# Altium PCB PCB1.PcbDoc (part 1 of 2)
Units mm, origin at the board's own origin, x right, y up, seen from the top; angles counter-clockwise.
Board outline 100 x 100 mm, 4 copper layers (Top Layer, Layer 1, Layer 2, Bottom Layer), stack 1.55 mm thick; 90 components, 49 nets, 314 pads, 474 vias.
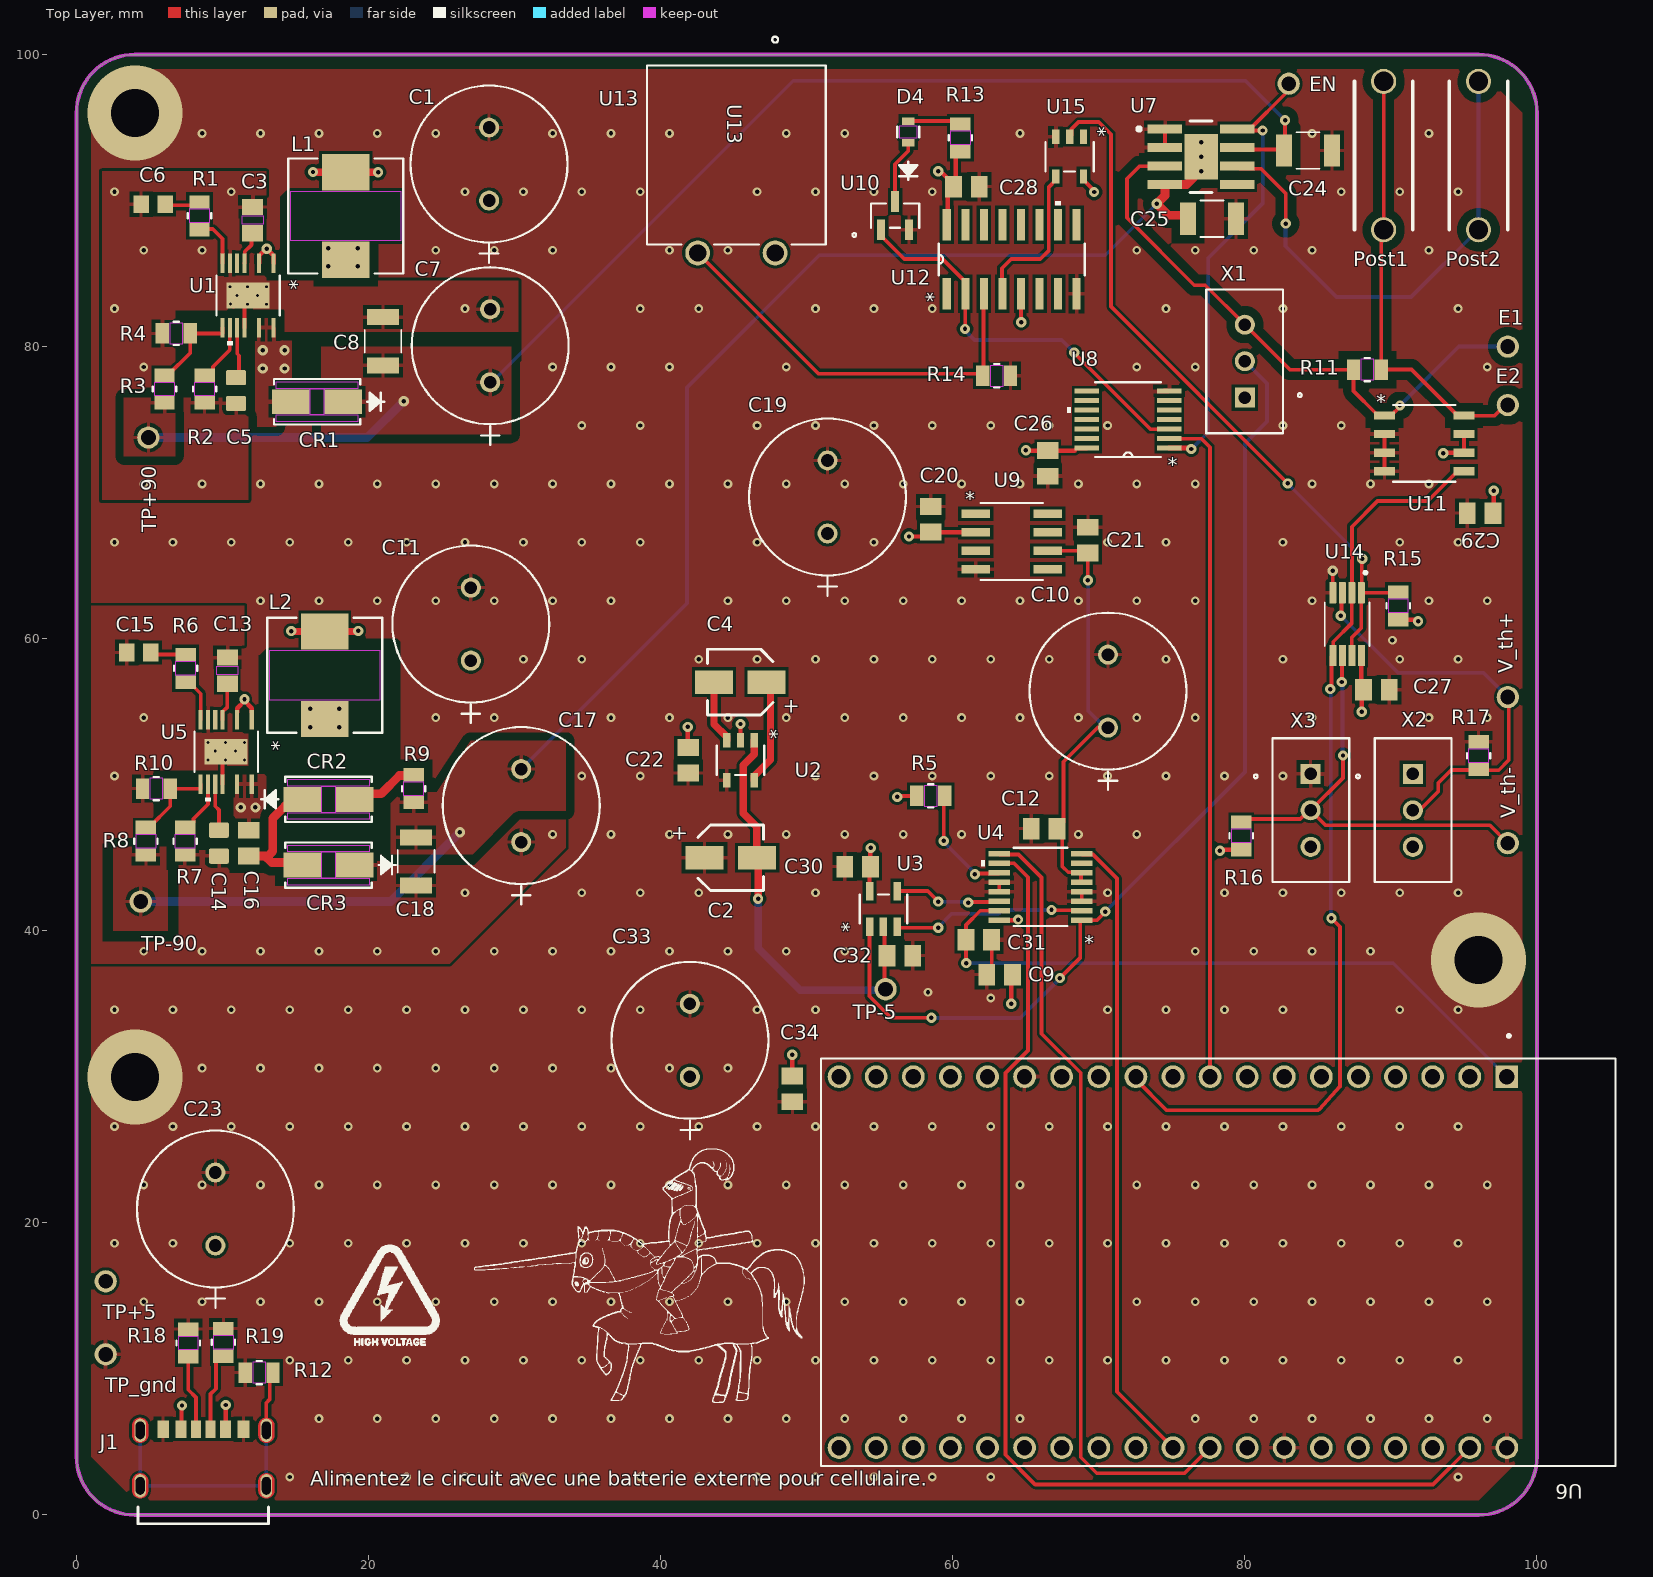
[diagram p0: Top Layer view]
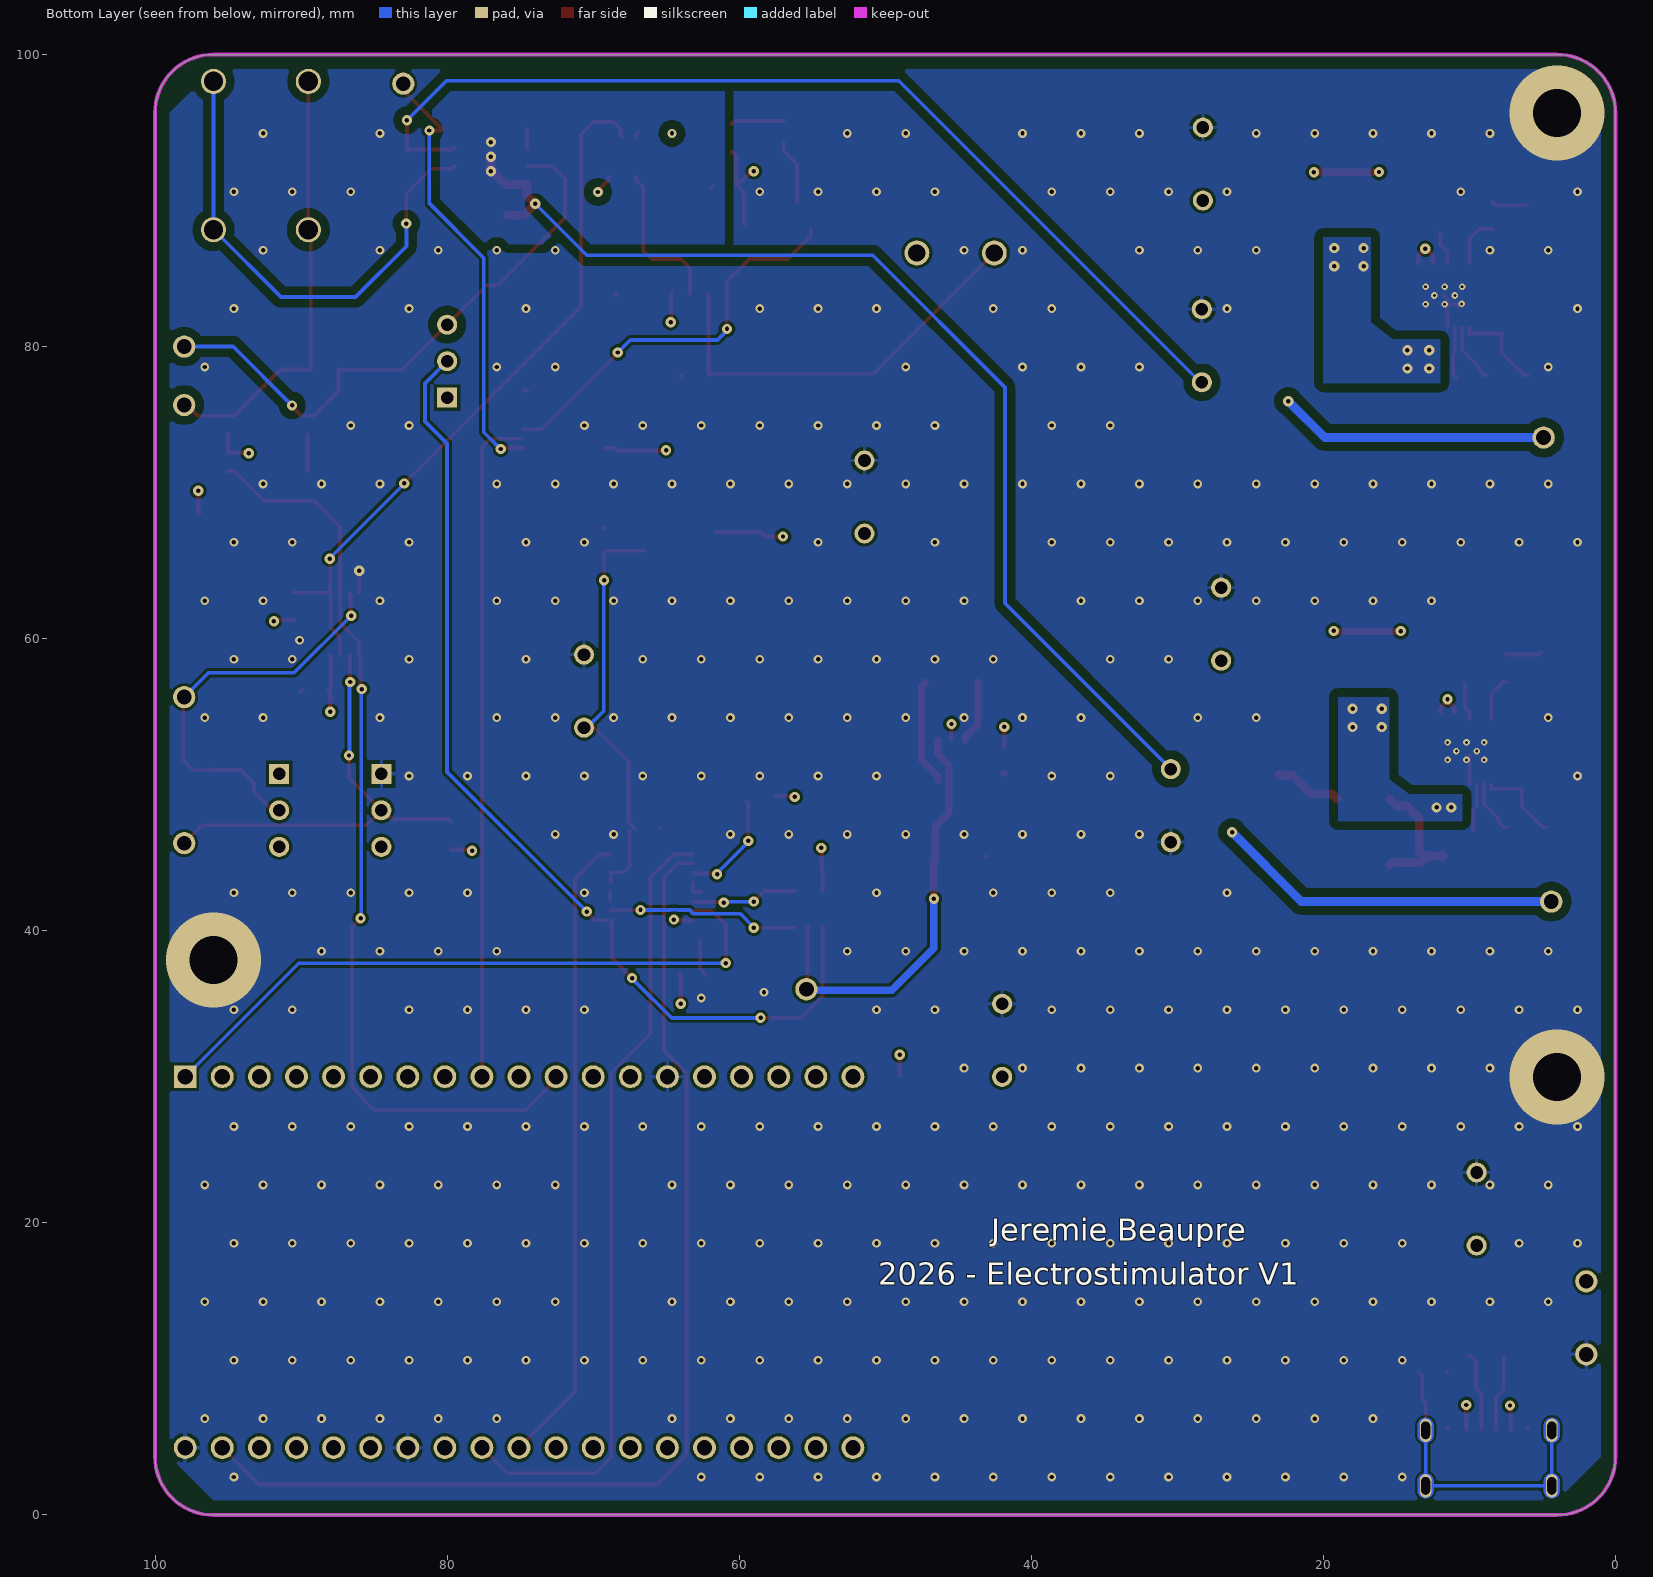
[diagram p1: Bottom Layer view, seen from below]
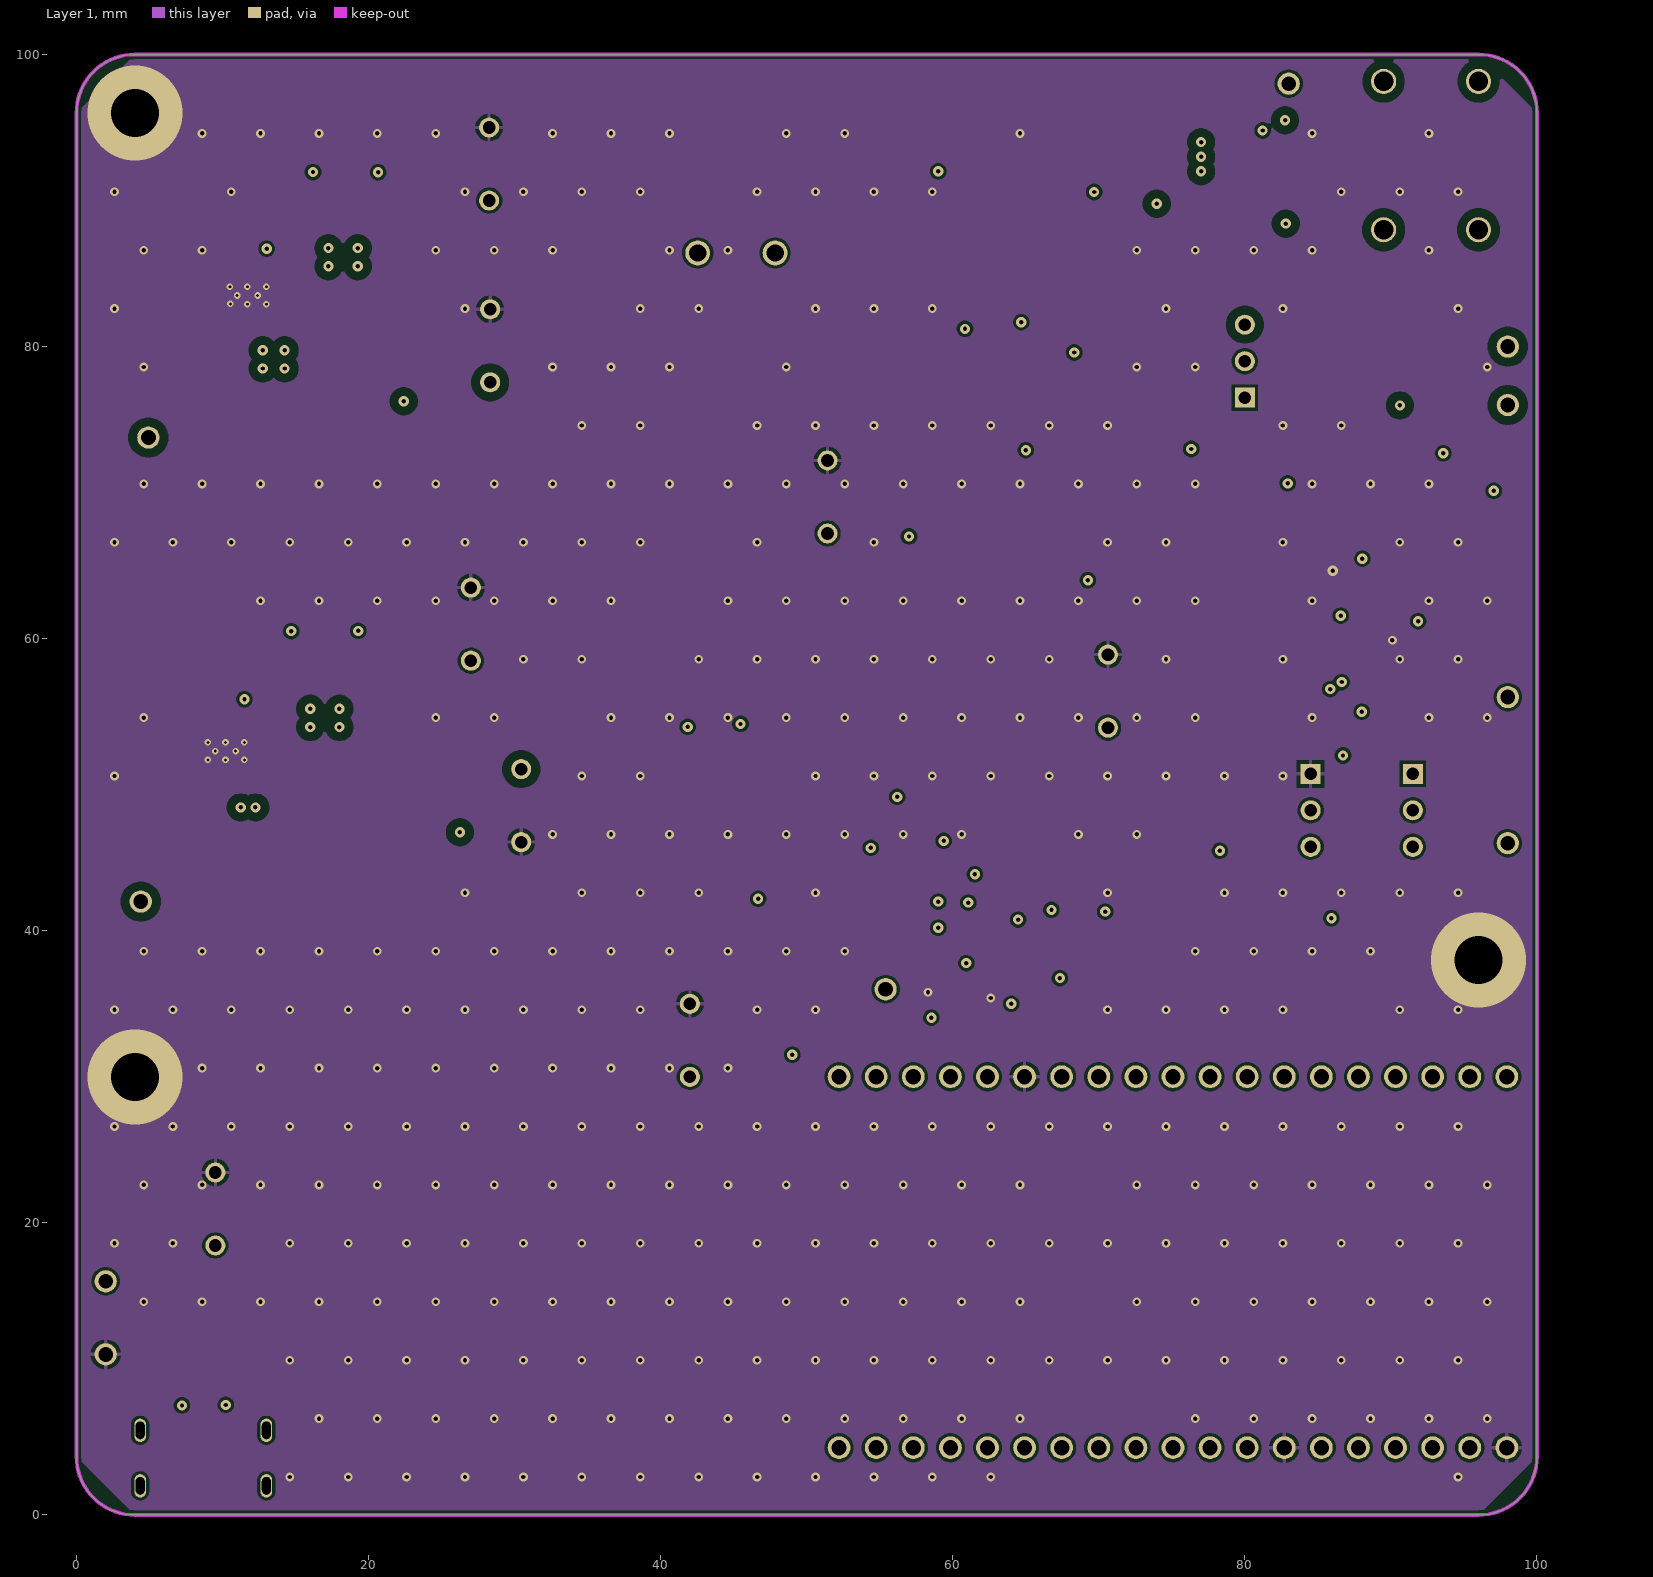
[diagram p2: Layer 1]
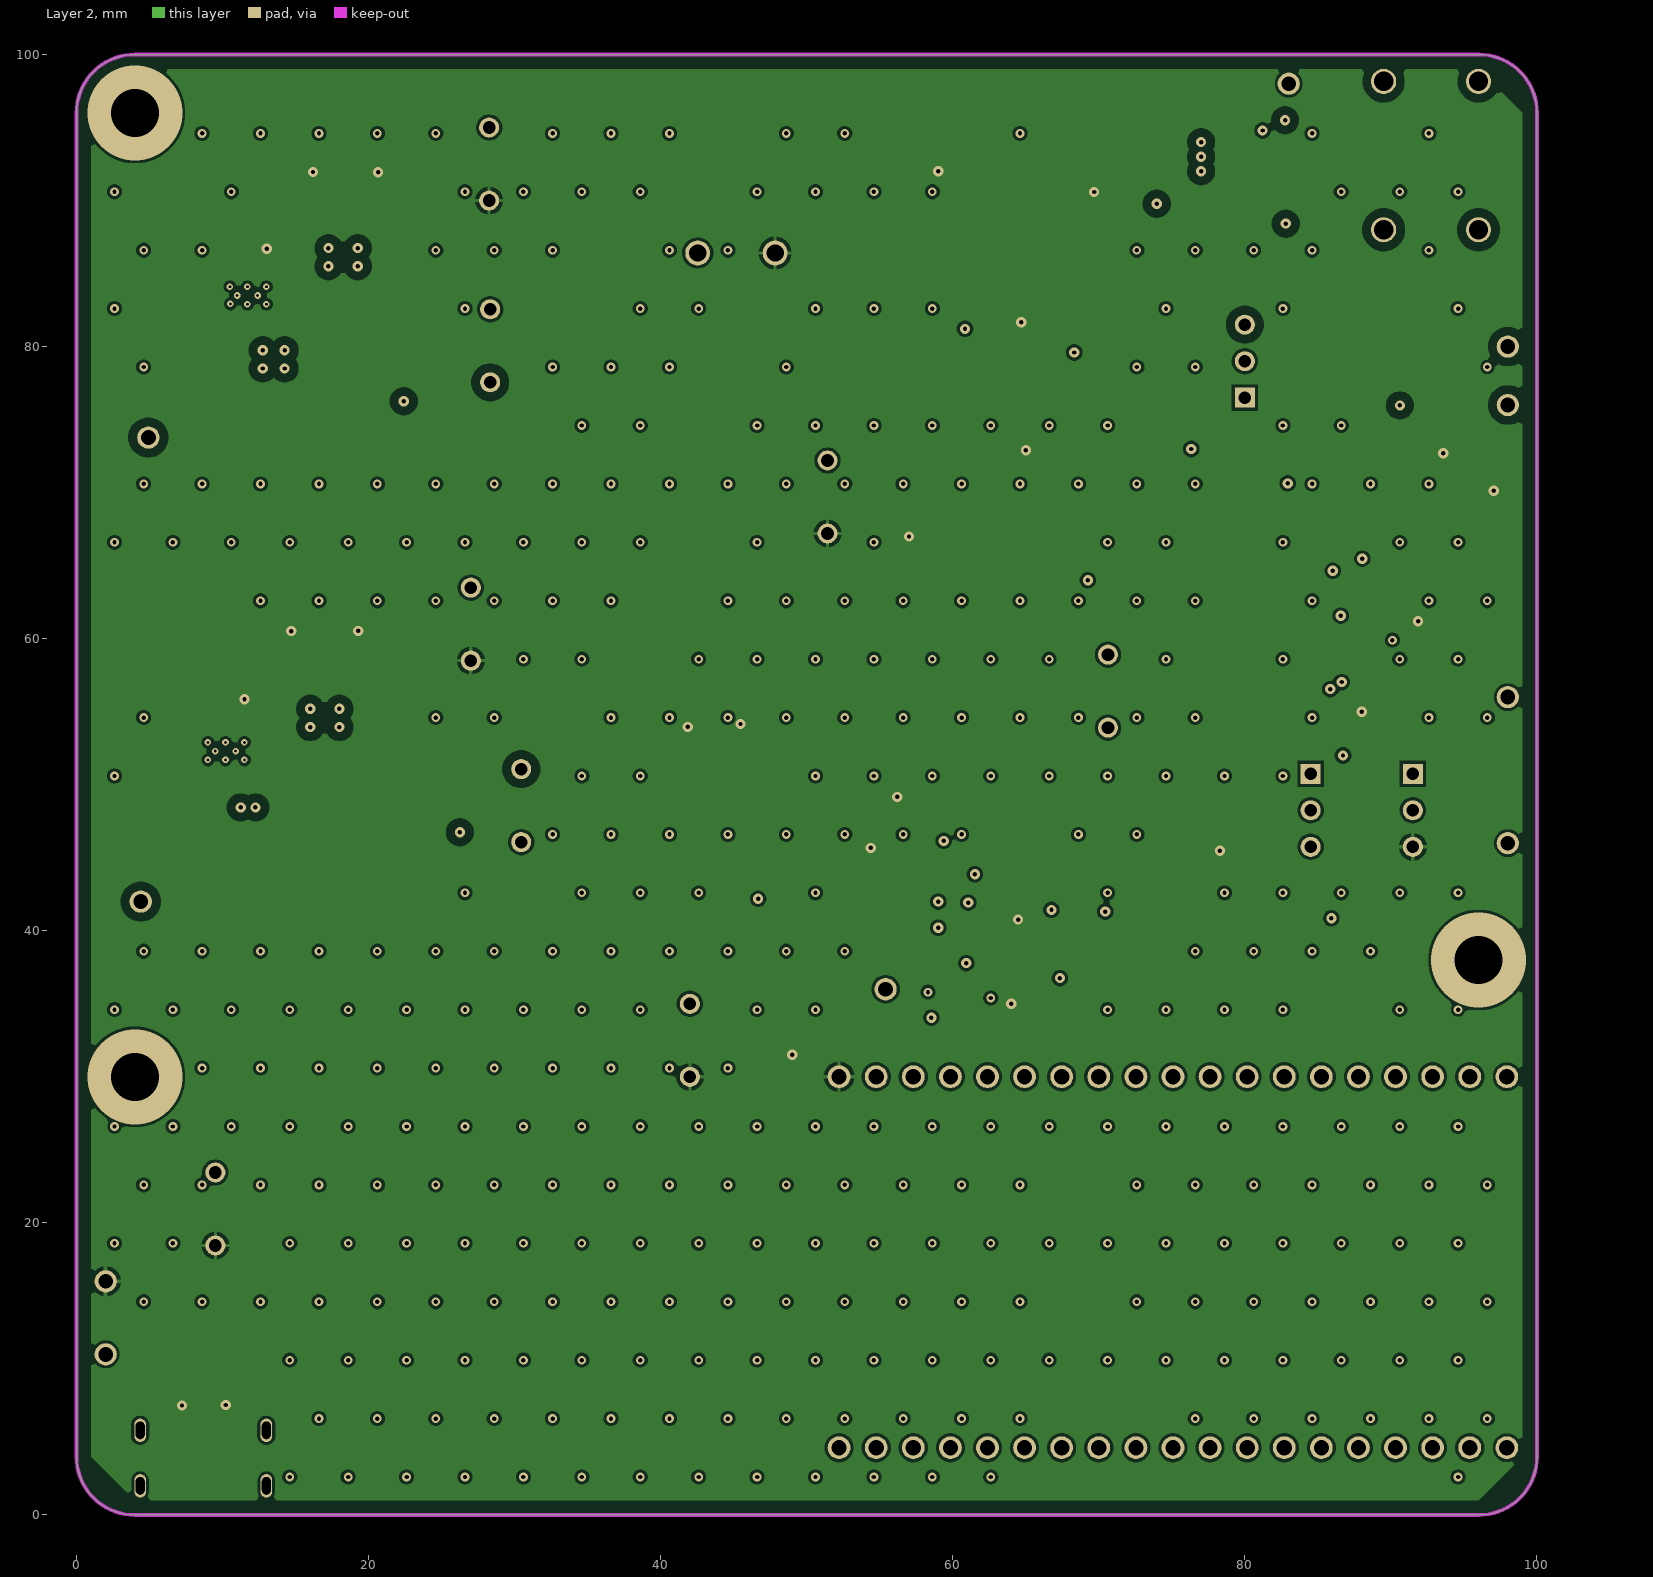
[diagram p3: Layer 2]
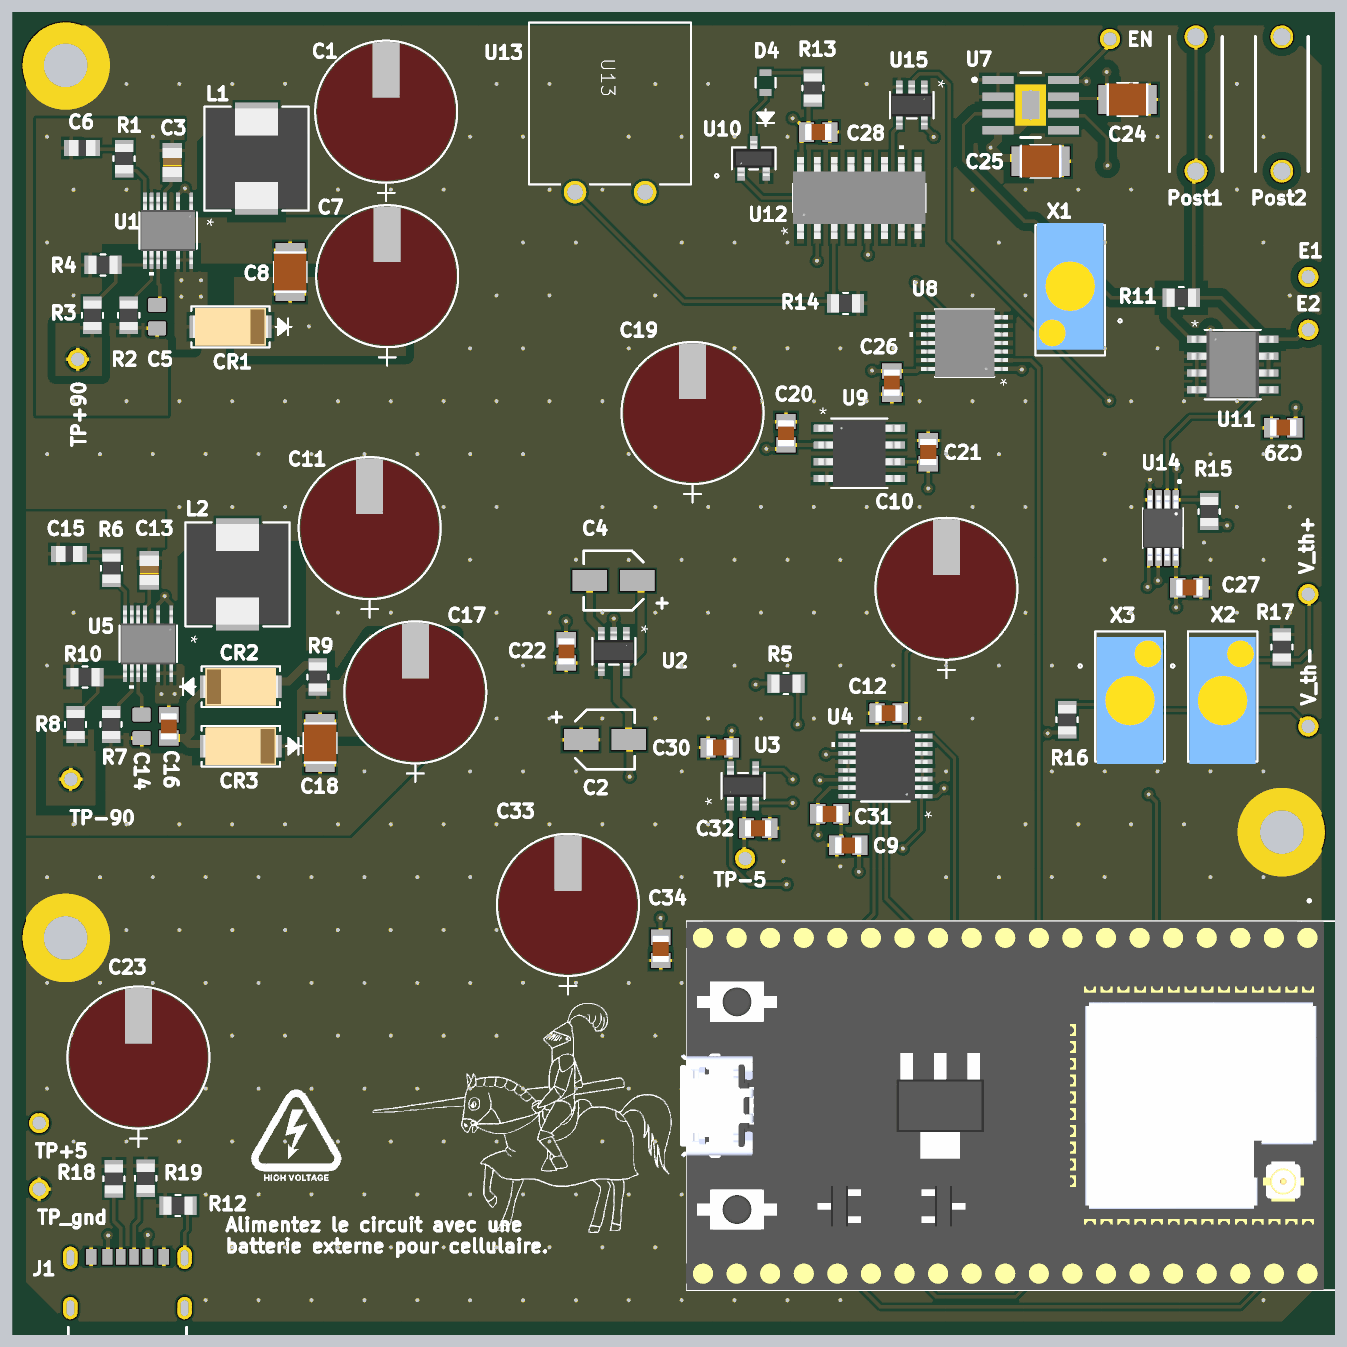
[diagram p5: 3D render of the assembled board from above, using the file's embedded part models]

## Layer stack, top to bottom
Top Solder: solder mask 0.0102, Solder Resist, Dk 3.5
Top Layer: signal copper 0.035
Dielectric 2: prepreg 0.19, PP-006, Dk 4.1
Layer 1: signal copper 0.035
Dielectric 1: core 1.03, Core-006, Dk 4.2
Layer 2: signal copper 0.035
Dielectric 3: prepreg 0.19, PP-006, Dk 4.1
Bottom Layer: signal copper 0.035
Bottom Solder: solder mask 0.0102, Solder Resist, Dk 3.5

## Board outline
0,4 0,96 cw(c4,96) 4,100 96,100 cw(c96,96) 100,96 100,4 cw(c96,4) 96,0 4,0 cw(c4,4)

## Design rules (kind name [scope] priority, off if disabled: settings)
Clearance HighVoltage [InNetClass('HighVoltage')] p1: gap=0.6 ignorepadtopadclearanceinfootprint=TRUE except(0.01: SMDPad-Region Region-Region; 0.152: Arc-Region Arc-Text Arc-Hole Track-Region Track-Text Track-Hole SMDPad-Text SMDPad-Hole THPad-Region THPad-Text THPad-Hole Via-Region Via-Text Via-Hole Fill-Region Fill-Text Fill-Hole Poly-Region Poly-Text Poly-Hole Region-Text Region-Hole Text-Text Text-Hole)
Clearance [All] p2: gap=0.2 ignorepadtopadclearanceinfootprint=TRUE except(0.01: SMDPad-Region Region-Region; 0.152: Track-Region)
HoleSize [All] p1: absolutevalues=TRUE maxlimit=6 minlimit=0.025 maxpercent=80.000 minpercent=20.000
MinimumSolderMaskSliver [All] p1: minsoldermaskwidth=0.1
PolygonConnect [All] p1: thpad.connectstyle=Relief thpad.reliefconductorwidth=0.254 thpad.reliefentries=4 thpad.polygonreliefangle="90 Angle" thpad.airgapwidth=0.254 smdpad.connectstyle=Relief smdpad.reliefconductorwidth=0.254 smdpad.reliefentries=4 smdpad.polygonreliefangle="90 Angle" smdpad.airgapwidth=0.254 via.connectstyle=Direct via.reliefconductorwidth=0.254 via.reliefentries=4 via.polygonreliefangle="90 Angle" via.airgapwidth=0.254
RoutingVias RoutingVias_small [All] p1: holewidth=0.3 width=0.7 viastyle="Through Hole" minholewidth=0.3 minwidth=0.7 maxholewidth=0.3 maxwidth=0.7
RoutingVias [All] p2: holewidth=0.711 width=6 viastyle="Through Hole" minholewidth=0.5 minwidth=0.7 maxholewidth=6 maxwidth=8
SolderMaskExpansion [All] p1: expansion=0.102 istentingtop=FALSE
SupplyNets "Schematic Supply Nets_17" [InNet('S1')] p1: voltage=0.000
SupplyNets "Schematic Supply Nets_16" [InNet('-5')] p2: voltage=0.000
SupplyNets "Schematic Supply Nets_15" [InNet('Electrode -')] p3: voltage=0.000
SupplyNets "Schematic Supply Nets_14" [InNet('EN_OPA2')] p4: voltage=0.000
SupplyNets "Schematic Supply Nets_13" [InNet('+5')] p5: voltage=0.000
SupplyNets "Schematic Supply Nets_12" [InNet('+90')] p6: voltage=0.000
SupplyNets "Schematic Supply Nets_11" [InNet('DIN')] p7: voltage=0.000
SupplyNets "Schematic Supply Nets_10" [InNet('+2.5')] p8: voltage=0.000
SupplyNets "Schematic Supply Nets_9" [InNet('V_th+')] p9: voltage=0.000
SupplyNets "Schematic Supply Nets_8" [InNet('CS')] p10: voltage=0.000
SupplyNets "Schematic Supply Nets_7" [InNet('+3.3')] p11: voltage=0.000
SupplyNets "Schematic Supply Nets_6" [InNet('Electrode +')] p12: voltage=0.000
SupplyNets "Schematic Supply Nets_5" [InNet('GND')] p13: voltage=0.000
SupplyNets "Schematic Supply Nets_4" [InNet('V_th-')] p14: voltage=0.000
SupplyNets "Schematic Supply Nets_3" [InNet('INV')] p15: voltage=0.000
SupplyNets "Schematic Supply Nets_2" [InNet('EN_OPA')] p16: voltage=0.000
SupplyNets "Schematic Supply Nets_1" [InNet('CLK')] p17: voltage=0.000
SupplyNets "Schematic Supply Nets" [InNet('-90')] p18: voltage=0.000
Width Power [InNet('+5')] p1: maxlimit=0.6 minlimit=0.3 preferedwidth=0.3 midlayer1_maxwidth=0.3 midlayer2_maxwidth=0.3 bottomlayer_maxwidth=0.3 minimp=50.000000 maximp=50.000000 favimp=50.000000
Width [All] p2: maxlimit=0.6 minlimit=0.2 preferedwidth=0.254
28 further rules are at their usual default settings.

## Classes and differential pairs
net class HighVoltage: +90 -90 "Electrode +" "Electrode -" NetC16_1 NetC16_2 NetCR1_2 NetCR2_2 NetE2_1
component class Sheet2: C27 C28 C29 D4 E1 E2 Post1 Post2 R11 R13 R14 R15 R16 R17 U10 U11 U12 U13 U14 U15 V_th+ V_th- X2 X3
component class Sheet1: C1 C2 C3 C4 C5 C6 C7 C8 C9 C10 C11 C12 C13 C14 C15 C16 C17 C18 C19 C20 C21 C22 C23 C24 C25 C26 C30 C31 C32 C33 C34 CR1 CR2 CR3 EN J1 L1 L2 R1 R2 R3 R4 R5 R6 R7 R8 R9 R10 R12 R18 R19 TP+5 TP+90 TP-5 TP-90 TP_gnd U1 U2 U3 U4 U5 U6 U7 U8 U9 X1

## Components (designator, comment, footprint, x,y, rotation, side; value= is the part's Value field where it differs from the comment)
C1 "10u" CAP_BX_10x20_RUB 28.25,90 r90 top
C2 "WCAP-ASLL_4X5.5" WCAP-ASLL_4X5.5(DXL) 44.8,45 r180 top
C3 "Capacitor" 0805_AVX 12.062,88.658 r90 top value=1u
C4 "WCAP-ASLL_4X5.5" WCAP-ASLL_4X5.5(DXL) 45.447,57.028 r0 top
C5 "Capacitor" CAPC2012X75N 10.922,76.992 r90 top value=2n
C6 "Capacitor" CC0805N_YAG 5.25,89.75 r0 top value=1n
C7 "10u" CAP_BX_10x20_RUB 28.324,77.556 r90 top
C8 "Capacitor" CAP_C3225X7R2E224K200AA 20.983,80.366 r270 top value=0.22u
C9 "Capacitor" CAPC2012X150N 63.2,37 r0 top value=0.1u
C10 "10u" CAP_BX_10x20_RUB 70.625,53.911 r90 top
C11 "10u" CAP_BX_10x20_RUB 27,58.5 r90 top
C12 "Capacitor" CAPC2012X150N 66.25,47 r0 top value=0.1u
C13 "Capacitor" 0805_AVX 10.33,57.807 r90 top value=1u
C14 "Capacitor" CAPC2012X75N 9.75,46 r90 top value=2n
C15 "Capacitor" CC0805N_YAG 4.268,59.049 r0 top value=1n
C16 "Capacitor" CAPC2012X150N 11.807,46.006 r90 top value=0.1u
C17 "10u" CAP_BX_10x20_RUB 30.45,46.073 r90 top
C18 "Capacitor" CAP_C3225X7R2E224K200AA 23.25,44.75 r90 top value=0.22u
C19 "10u" CAP_BX_10x20_RUB 51.423,67.205 r90 top
C20 "Capacitor" CAPC2012X150N 58.491,68.177 r270 top value=0.1u
C21 "Capacitor" CAPC2012X150N 69.25,66.75 r270 top value=0.1u
C22 "Capacitor" CAPC2012X150N 41.874,51.679 r270 top value=0.1u
C23 "10u" CAP_BX_10x20_RUB 9.509,18.452 r90 top
C24 "Capacitor" CAP_C3225X7R2E224K200AA 84.323,93.423 r180 top value=0.22u
C25 "Capacitor" CAP_C3225X7R2E224K200AA 77.75,88.75 r0 top value=0.22u
C26 "Capacitor" CAPC2012X150N 66.5,72 r270 top value=0.1u
C27 "Capacitor" CAPC2012X150N 89,56.5 r180 top value=0.1u
C28 "Capacitor" CAPC2012X150N 60.93,90.958 r180 top value=0.1u
C29 "Capacitor" CAPC2012X150N 96.1,68.6 r0 top value=0.1u
C30 "Capacitor" CAPC2012X150N 53.48,44.4 r0 top value=0.1u
C31 "Capacitor" CAPC2012X150N 61.779,39.383 r180 top value=0.1u
C32 "Capacitor" CAPC2012X150N 56.38,38.3 r180 top value=0.1u
C33 "10u" CAP_BX_10x20_RUB 42,30 r90 top
C34 "Capacitor" CAPC2012X150N 49.017,29.174 r90 top value=0.1u
CR1 "SK220ATR" DIODE_SK220ATR_SMC-M 16.473,76.224 r180 top
CR2 "SK220ATR" DIODE_SK220ATR_SMC-M 17.25,49 r0 top
CR3 "SK220ATR" DIODE_SK220ATR_SMC-M 17.25,44.5 r180 top
D4 "SML-M13UTT86" LED_SML-M13DT_ROM 56.949,94.694 r90 top
E1 "Testpoint_1" Testpoint1 98,80 r0 top
E2 "Testpoint_1" Testpoint1 98,76 r0 top
EN "Testpoint_1" Testpoint1 83,98 r0 top
J1 "USB4125-GF-A_REVA2" GCT_USB4125-GF-A_REVA2 8.68,2.8 r0 top
L1 "Inductor" DR73 18.44,88.946 r270 top value=10u
L2 "Inductor" DR73 17,57.5 r270 top value=10u
Post1 "J110-ND" J110-ND 89.5,88 r90 top
Post2 "J110-ND" J110-ND 96,88 r90 top
R1 "Resistor" RESISTOR_0805-M 8.422,88.946 r270 top value=84.5K
R2 "Resistor" RESISTOR_0805-M 8.774,77.097 r90 top value=107K
R3 "Resistor" RESISTOR_0805-M 6.028,77.097 r270 top value=1MEG
R4 "Resistor" RESISTOR_0805-M 6.829,80.903 r180 top value=18.1K
R5 "Resistor" RESISTOR_0805-M 58.491,49.234 r0 top value=10k
R6 "Resistor" RESISTOR_0805-M 7.467,57.968 r270 top value=84.5K
R7 "Resistor" RESISTOR_0805-M 7.436,46.146 r90 top value=107K
R8 "1MEG" RESISTOR_0805-M 4.751,46.146 r90 top
R9 "Resistor" RESISTOR_0805-M 23.085,49.735 r270 top value=20
R10 "Resistor" RESISTOR_0805-M 5.467,49.735 r180 top value=8.96k
R11 "Resistor" RESISTOR_0805-M 88.391,78.427 r0 top value=1
R12 "Resistor" RESISTOR_0805-M 12.5,9.75 r180 top value=1MEG
R13 "Resistor" RESISTOR_0805-M 60.524,94.288 r270 top value=350
R14 "Resistor" RESISTOR_0805-M 63,78 r0 top value=10K
R15 "Resistor" RESISTOR_0805-M 90.5,62.25 r270 top value=10K
R16 "Resistor" RESISTOR_0805-M 79.75,46.5 r270 top value=1K
R17 "Resistor" RESISTOR_0805-M 96,52 r270 top value=1K
R18 "Resistor" RESISTOR_0805-M 7.651,11.776 r270 top value=5.1k
R19 "Resistor" RESISTOR_0805-M 10.058,11.815 r270 top value=5.1k
TP+5 "Testpoint_1" Testpoint1 2,16 r90 top
TP+90 "Testpoint_1" Testpoint1 4.921,73.772 r0 top
TP-5 "Testpoint_1" Testpoint1 55.4,36 r270 top
TP-90 "Testpoint_1" Testpoint1 4.4,42 r90 top
TP_gnd "Testpoint_1" Testpoint1 2,11 r90 top
U1 "LT8365HMSE#PBF" 05-08-1871_ADI 11.75,83.5 r270 top
U2 "MAX870EUK+T" 21-0057F_MXM 45.467,51.679 r270 top
U3 "AD8628ARTZ-REEL7" RJ_5_ADI 55.25,41.5 r90 top
U4 "AD5542ABRUZ" RU_16_ADI 66,43 r180 top
U5 "LT8365HMSE#PBF" 05-08-1871_ADI 10.25,52.25 r270 top
U6 "ESP32-DEVKITC-32UE" ESPRESSIF_ESP32-DEVKITC-32UE 75.075,17.308 r270 top
U7 "OPA462IDDA" DDA0008J-IPC_A 77,93 r0 top
U8 "SN74HC02PWR" PW14 72,75 r180 top
U9 "ADR421ARZ" R_8_ADI 64.036,66.655 r0 top
U10 "2N7002KT1G" SOT-23_ONS 56.048,88.965 r0 top
U11 "INA240A1DR" D8_TEX 92.281,73.37 r0 top
U12 "CD4043BDR" D16 64.036,85.979 r90 top
U13 "GPTS203211B" SWITCH_03211B 47.834,86.411 r270 top
U14 "TLV1702AIDGKR" SOP65P490X110-8N 87,61 r270 top
U15 "SN74AHC1G04DBVR" DBV5 68,93 r270 top
V_th+ "Testpoint_1" Testpoint1 98,56 r270 top
V_th- "Testpoint_1" Testpoint1 98,46 r270 top
X1 "PV36W102C01B00" POT_PV36W_MUR 80,76.5 r90 top
X2 "PV36W102C01B00" POT_PV36W_MUR 91.5,50.75 r270 top
X3 "PV36W102C01B00" POT_PV36W_MUR 84.5,50.75 r270 top

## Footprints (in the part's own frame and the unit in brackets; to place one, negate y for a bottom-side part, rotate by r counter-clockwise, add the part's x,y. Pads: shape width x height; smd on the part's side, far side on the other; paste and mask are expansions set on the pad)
05-08-1871_ADI [mil]
  rect 52.5x11 smd paste+0 mask+0: 1(-87.25,68.9) 3(-87.25,29.53) 5(-87.25,-9.84) 6(-87.25,-29.53) 7(-87.25,-49.21) 8(-87.25,-68.9) 9(87.25,-68.9) 10(87.25,-49.21) 11(87.25,-29.53) 12(87.25,-9.84) 14(87.25,29.53) 16(87.25,68.9)
  rect 69x116 smd paste-57.5 mask+0: 17(0,0)
  silkscreen extent -54,-86 134,86, body extent -99,-81 99,81, height 43
21-0057F_MXM [mil]
  rect 38.5x20 smd paste+0 mask+0: 1(-53.75,37.4) 2(-53.75,0) 3(-53.75,-37.4) 4(53.75,-37.4) 5(53.75,37.4)
  silkscreen extent -40,-64 40,64, body extent -59,-59 59,59, height 57
0805_AVX [mil]
  rect 44x57 smd paste+0 mask+0: 1(-35.5,0) 2(35.5,0)
  Top Layer keep-out region: -11.5,-28.5 -11.5,28.5 11.5,28.5 11.5,-28.5
  body extent -44,-29 44,29, height 37
CAP_BX_10x20_RUB [mil]
  round 54 hole 34 paste-99999 mask+0: 1(0,0) 2(196.85,0)
  silkscreen extent -168,-212 310,212, body extent -108,-206 306,206, height 867
CAP_C3225X7R2E224K200AA [mm]
  rect 1.1x2.2 smd: 1(-1.65,0) 2(1.65,0)
  silkscreen extent -0.78,-1.25 0.78,1.25, body extent -1.6,-1.25 1.6,1.25, height 2.2
CAPC2012X75N [mm]
  rrect25% 1.05x1.38 smd: 1(-0.888,0) 2(0.888,0)
CAPC2012X150N [mm]
  rect 1.15x1.47 smd: 1(-0.88,0) 2(0.88,0)
  body extent -1,-0.63 1,0.63, height 1.5
CC0805N_YAG [mil]
  rect 42x48 smd paste+0 mask+0: 1(-32.5,0) 2(32.5,0)
  body extent -39,-24 39,24, height 28
D8_TEX [mm]
  rect 1.455x0.558 smd paste+0 mask+0: 1(-2.721,1.905) 2(-2.721,0.635) 3(-2.721,-0.635) 4(-2.721,-1.905) 5(2.721,-1.905) 6(2.721,-0.635) 7(2.721,0.635) 8(2.721,1.905)
  silkscreen extent -2.12,-2.63 2.12,2.63, body extent -3.1,-2.5 3.1,2.5, height 1.76
D16 [mil]
  rect 86x22 smd paste-43 mask-43: 1(-93,175) 2(-93,125) 3(-93,75) 4(-93,25) 5(-93,-25) 6(-93,-75) 7(-93,-125) 8(-93,-175) 9(93,-175) 10(93,-125) 11(93,-75) 12(93,-25) 13(93,25) 14(93,75) 15(93,125) 16(93,175)
  silkscreen extent -43,-197 156,197, body extent -122,-197 122,197, height 69
DBV5 [mil]
  rect 38.28x20 smd paste+0 mask+0: 1(-53.64,37.4) 2(-53.64,0) 3(-53.64,-37.4) 4(53.64,-37.4) 5(53.64,37.4)
  silkscreen extent -40,-65 40,65, body extent -59,-60 59,60, height 57
DDA0008J-IPC_A [mm]
  rect 2.353x0.622 smd paste+0 mask+0: 1(-2.477,1.905) 2(-2.477,0.635) 3(-2.477,-0.635) 4(-2.477,-1.905) 5(2.477,-1.905) 6(2.477,-0.635) 7(2.477,0.635) 8(2.477,1.905)
  rect 2.3x3.1 smd paste-1.537 mask+0: 9(0,0)
  silkscreen extent -4.37,-2.45 0.75,2.45
DIODE_SK220ATR_SMC-M [mil]
  rect 101x67 smd paste+0 mask+0: 1(-71,0) 2(71,0)
  Top Layer keep-out region: -18.5,-35.5 -18.5,35.5 18.5,35.5 18.5,-35.5
  Top Layer keep-out region: -109.5,35.5 -109.5,54 109.5,54 109.5,35.5
  Top Layer keep-out region: -109.5,-54 -109.5,-35.5 109.5,-35.5 109.5,-54
  silkscreen extent -182,-61 117,61, body extent -111,-56 111,56, height 118
DR73 [mil]
  rect 98x128 smd paste+0 mask+0: 1(-118,0) 2(118,0)
  Top Layer keep-out region: -67,-148 -67,148 67,148 67,-148
  silkscreen extent -155,-155 155,155, body extent -150,-150 150,150, height 140
ESPRESSIF_ESP32-DEVKITC-32UE [mm]
  rect 1.56x1.56 / inner round 1.56 / far side rect 1.56x1.56 hole 1.04: 1(-12.7,22.86)
  round 1.56 hole 1.04: 2(-12.7,20.32) 3(-12.7,17.78) 4(-12.7,15.24) 5(-12.7,12.7) 6(-12.7,10.16) 7(-12.7,7.62) 8(-12.7,5.08) 9(-12.7,2.54) 10(-12.7,0) 11(-12.7,-2.54) 12(-12.7,-5.08) 13(-12.7,-7.62) 14(-12.7,-10.16) 15(-12.7,-12.7) 16(-12.7,-15.24) 17(-12.7,-17.78) 18(-12.7,-20.32) 19(-12.7,-22.86) 20(12.7,22.86) 21(12.7,20.32) 22(12.7,17.78) 23(12.7,15.24) 24(12.7,12.7) 25(12.7,10.16) 26(12.7,7.62) 27(12.7,5.08) 28(12.7,2.54) 29(12.7,0) 30(12.7,-2.54) 31(12.7,-5.08) 32(12.7,-7.62) 33(12.7,-10.16) 34(12.7,-12.7) 35(12.7,-15.24) 36(12.7,-17.78) 37(12.7,-20.32) 38(12.7,-22.86)
  silkscreen extent -15.6,-24.1 13.95,30.3, body extent -13.95,-24.62 13.95,24.13, height 7.85
GCT_USB4125-GF-A_REVA2 [mm]
  rect 0.7x1.2 smd: A5(-0.5,3.08) B5(0.5,3.08)
  rect 0.76x1.2 smd: A9(1.52,3.08) B9(-1.52,3.08)
  rect 0.8x1.2 smd: A12(2.75,3.08) B12(-2.75,3.08)
  oval 0.8x1.6 hole 0.6 slot 1.2 at 90 deg mask+0: S1(-4.32,3) S2(4.32,3) S3(-4.32,-0.8) S4(4.32,-0.8)
  Top Layer region: 4.349,0.049 4.377,0.047 4.406,0.043 4.434,0.038 4.462,0.031 4.49,0.023 4.517,0.013 4.544,0.002 4.57,-0.01 4.595,-0.024 4.62,-0.039 4.643,-0.055 4.666,-0.073 4.688,-0.091 4.709,-0.111 4.729,-0.132 4.747,-0.154 4.765,-0.177 4.781,-0.2 4.796,-0.225 4.81,-0.25 4.822,-0.276 4.833,-0.303 4.843,-0.33 4.851,-0.358 4.858,-0.386 4.863,-0.414 4.867,-0.443 4.869,-0.471 4.87,-0.5 4.87,-1.1 4.869,-1.129 4.867,-1.157 4.863,-1.186 4.858,-1.214 4.851,-1.242 4.843,-1.27 4.833,-1.297 4.822,-1.324 4.81,-1.35 4.796,-1.375 4.781,-1.4 4.765,-1.423 4.747,-1.446 4.729,-1.468 4.709,-1.489 4.688,-1.509 4.666,-1.527 4.643,-1.545 4.62,-1.561 4.595,-1.576 4.57,-1.59 4.544,-1.602 4.517,-1.613 4.49,-1.623 4.462,-1.631 4.434,-1.638 4.406,-1.643 4.377,-1.647 4.349,-1.649 4.32,-1.65 4.291,-1.649 4.263,-1.647 4.234,-1.643 4.206,-1.638 4.178,-1.631 4.15,-1.623 4.123,-1.613 4.096,-1.602 4.07,-1.59 4.045,-1.576 4.02,-1.561 3.997,-1.545 3.974,-1.527 3.952,-1.509 3.931,-1.489 3.911,-1.468 3.893,-1.446 3.875,-1.423 3.859,-1.4 3.844,-1.375 3.83,-1.35 3.818,-1.324 3.807,-1.297 3.797,-1.27 3.789,-1.242 3.782,-1.214 3.777,-1.186 3.773,-1.157 3.771,-1.129 3.77,-1.1 3.77,-0.5 3.771,-0.471 3.773,-0.443 3.777,-0.414 3.782,-0.386 3.789,-0.358 3.797,-0.33 3.807,-0.303 3.818,-0.276 3.83,-0.25 3.844,-0.225 3.859,-0.2 3.875,-0.177 3.893,-0.154 3.911,-0.132 3.931,-0.111 3.952,-0.091 3.974,-0.073 3.997,-0.055 4.02,-0.039 4.045,-0.024 4.07,-0.01 4.096,0.002 4.123,0.013 4.15,0.023 4.178,0.031 4.206,0.038 4.234,0.043 4.263,0.047 4.291,0.049 4.32,0.05
  Top Layer region: 4.349,3.849 4.377,3.847 4.406,3.843 4.434,3.838 4.462,3.831 4.49,3.823 4.517,3.813 4.544,3.802 4.57,3.79 4.595,3.776 4.62,3.761 4.643,3.745 4.666,3.727 4.688,3.709 4.709,3.689 4.729,3.668 4.747,3.646 4.765,3.623 4.781,3.6 4.796,3.575 4.81,3.55 4.822,3.524 4.833,3.497 4.843,3.47 4.851,3.442 4.858,3.414 4.863,3.386 4.867,3.357 4.869,3.329 4.87,3.3 4.87,2.7 4.869,2.671 4.867,2.643 4.863,2.614 4.858,2.586 4.851,2.558 4.843,2.53 4.833,2.503 4.822,2.476 4.81,2.45 4.796,2.425 4.781,2.4 4.765,2.377 4.747,2.354 4.729,2.332 4.709,2.311 4.688,2.291 4.666,2.273 4.643,2.255 4.62,2.239 4.595,2.224 4.57,2.21 4.544,2.198 4.517,2.187 4.49,2.177 4.462,2.169 4.434,2.162 4.406,2.157 4.377,2.153 4.349,2.151 4.32,2.15 4.291,2.151 4.263,2.153 4.234,2.157 4.206,2.162 4.178,2.169 4.15,2.177 4.123,2.187 4.096,2.198 4.07,2.21 4.045,2.224 4.02,2.239 3.997,2.255 3.974,2.273 3.952,2.291 3.931,2.311 3.911,2.332 3.893,2.354 3.875,2.377 3.859,2.4 3.844,2.425 3.83,2.45 3.818,2.476 3.807,2.503 3.797,2.53 3.789,2.558 3.782,2.586 3.777,2.614 3.773,2.643 3.771,2.671 3.77,2.7 3.77,3.3 3.771,3.329 3.773,3.357 3.777,3.386 3.782,3.414 3.789,3.442 3.797,3.47 3.807,3.497 3.818,3.524 3.83,3.55 3.844,3.575 3.859,3.6 3.875,3.623 3.893,3.646 3.911,3.668 3.931,3.689 3.952,3.709 3.974,3.727 3.997,3.745 4.02,3.761 4.045,3.776 4.07,3.79 4.096,3.802 4.123,3.813 4.15,3.823 4.178,3.831 4.206,3.838 4.234,3.843 4.263,3.847 4.291,3.849 4.32,3.85
  Top Layer region: -4.291,3.849 -4.263,3.847 -4.234,3.843 -4.206,3.838 -4.178,3.831 -4.15,3.823 -4.123,3.813 -4.096,3.802 -4.07,3.79 -4.045,3.776 -4.02,3.761 -3.997,3.745 -3.974,3.727 -3.952,3.709 -3.931,3.689 -3.911,3.668 -3.893,3.646 -3.875,3.623 -3.859,3.6 -3.844,3.575 -3.83,3.55 -3.818,3.524 -3.807,3.497 -3.797,3.47 -3.789,3.442 -3.782,3.414 -3.777,3.386 -3.773,3.357 -3.771,3.329 -3.77,3.3 -3.77,2.7 -3.771,2.671 -3.773,2.643 -3.777,2.614 -3.782,2.586 -3.789,2.558 -3.797,2.53 -3.807,2.503 -3.818,2.476 -3.83,2.45 -3.844,2.425 -3.859,2.4 -3.875,2.377 -3.893,2.354 -3.911,2.332 -3.931,2.311 -3.952,2.291 -3.974,2.273 -3.997,2.255 -4.02,2.239 -4.045,2.224 -4.07,2.21 -4.096,2.198 -4.123,2.187 -4.15,2.177 -4.178,2.169 -4.206,2.162 -4.234,2.157 -4.263,2.153 -4.291,2.151 -4.32,2.15 -4.349,2.151 -4.377,2.153 -4.406,2.157 -4.434,2.162 -4.462,2.169 -4.49,2.177 -4.517,2.187 -4.544,2.198 -4.57,2.21 -4.595,2.224 -4.62,2.239 -4.643,2.255 -4.666,2.273 -4.688,2.291 -4.709,2.311 -4.729,2.332 -4.747,2.354 -4.765,2.377 -4.781,2.4 -4.796,2.425 -4.81,2.45 -4.822,2.476 -4.833,2.503 -4.843,2.53 -4.851,2.558 -4.858,2.586 -4.863,2.614 -4.867,2.643 -4.869,2.671 -4.87,2.7 -4.87,3.3 -4.869,3.329 -4.867,3.357 -4.863,3.386 -4.858,3.414 -4.851,3.442 -4.843,3.47 -4.833,3.497 -4.822,3.524 -4.81,3.55 -4.796,3.575 -4.781,3.6 -4.765,3.623 -4.747,3.646 -4.729,3.668 -4.709,3.689 -4.688,3.709 -4.666,3.727 -4.643,3.745 -4.62,3.761 -4.595,3.776 -4.57,3.79 -4.544,3.802 -4.517,3.813 -4.49,3.823 -4.462,3.831 -4.434,3.838 -4.406,3.843 -4.377,3.847 -4.349,3.849 -4.32,3.85
  Top Layer region: -4.291,0.049 -4.263,0.047 -4.234,0.043 -4.206,0.038 -4.178,0.031 -4.15,0.023 -4.123,0.013 -4.096,0.002 -4.07,-0.01 -4.045,-0.024 -4.02,-0.039 -3.997,-0.055 -3.974,-0.073 -3.952,-0.091 -3.931,-0.111 -3.911,-0.132 -3.893,-0.154 -3.875,-0.177 -3.859,-0.2 -3.844,-0.225 -3.83,-0.25 -3.818,-0.276 -3.807,-0.303 -3.797,-0.33 -3.789,-0.358 -3.782,-0.386 -3.777,-0.414 -3.773,-0.443 -3.771,-0.471 -3.77,-0.5 -3.77,-1.1 -3.771,-1.129 -3.773,-1.157 -3.777,-1.186 -3.782,-1.214 -3.789,-1.242 -3.797,-1.27 -3.807,-1.297 -3.818,-1.324 -3.83,-1.35 -3.844,-1.375 -3.859,-1.4 -3.875,-1.423 -3.893,-1.446 -3.911,-1.468 -3.931,-1.489 -3.952,-1.509 -3.974,-1.527 -3.997,-1.545 -4.02,-1.561 -4.045,-1.576 -4.07,-1.59 -4.096,-1.602 -4.123,-1.613 -4.15,-1.623 -4.178,-1.631 -4.206,-1.638 -4.234,-1.643 -4.263,-1.647 -4.291,-1.649 -4.32,-1.65 -4.349,-1.649 -4.377,-1.647 -4.406,-1.643 -4.434,-1.638 -4.462,-1.631 -4.49,-1.623 -4.517,-1.613 -4.544,-1.602 -4.57,-1.59 -4.595,-1.576 -4.62,-1.561 -4.643,-1.545 -4.666,-1.527 -4.688,-1.509 -4.709,-1.489 -4.729,-1.468 -4.747,-1.446 -4.765,-1.423 -4.781,-1.4 -4.796,-1.375 -4.81,-1.35 -4.822,-1.324 -4.833,-1.297 -4.843,-1.27 -4.851,-1.242 -4.858,-1.214 -4.863,-1.186 -4.867,-1.157 -4.869,-1.129 -4.87,-1.1 -4.87,-0.5 -4.869,-0.471 -4.867,-0.443 -4.863,-0.414 -4.858,-0.386 -4.851,-0.358 -4.843,-0.33 -4.833,-0.303 -4.822,-0.276 -4.81,-0.25 -4.796,-0.225 -4.781,-0.2 -4.765,-0.177 -4.747,-0.154 -4.729,-0.132 -4.709,-0.111 -4.688,-0.091 -4.666,-0.073 -4.643,-0.055 -4.62,-0.039 -4.595,-0.024 -4.57,-0.01 -4.544,0.002 -4.517,0.013 -4.49,0.023 -4.462,0.031 -4.434,0.038 -4.406,0.043 -4.377,0.047 -4.349,0.049 -4.32,0.05
  Bottom Layer region: 4.349,3.849 4.377,3.847 4.406,3.843 4.434,3.838 4.462,3.831 4.49,3.823 4.517,3.813 4.544,3.802 4.57,3.79 4.595,3.776 4.62,3.761 4.643,3.745 4.666,3.727 4.688,3.709 4.709,3.689 4.729,3.668 4.747,3.646 4.765,3.623 4.781,3.6 4.796,3.575 4.81,3.55 4.822,3.524 4.833,3.497 4.843,3.47 4.851,3.442 4.858,3.414 4.863,3.386 4.867,3.357 4.869,3.329 4.87,3.3 4.87,2.7 4.869,2.671 4.867,2.643 4.863,2.614 4.858,2.586 4.851,2.558 4.843,2.53 4.833,2.503 4.822,2.476 4.81,2.45 4.796,2.425 4.781,2.4 4.765,2.377 4.747,2.354 4.729,2.332 4.709,2.311 4.688,2.291 4.666,2.273 4.643,2.255 4.62,2.239 4.595,2.224 4.57,2.21 4.544,2.198 4.517,2.187 4.49,2.177 4.462,2.169 4.434,2.162 4.406,2.157 4.377,2.153 4.349,2.151 4.32,2.15 4.291,2.151 4.263,2.153 4.234,2.157 4.206,2.162 4.178,2.169 4.15,2.177 4.123,2.187 4.096,2.198 4.07,2.21 4.045,2.224 4.02,2.239 3.997,2.255 3.974,2.273 3.952,2.291 3.931,2.311 3.911,2.332 3.893,2.354 3.875,2.377 3.859,2.4 3.844,2.425 3.83,2.45 3.818,2.476 3.807,2.503 3.797,2.53 3.789,2.558 3.782,2.586 3.777,2.614 3.773,2.643 3.771,2.671 3.77,2.7 3.77,3.3 3.771,3.329 3.773,3.357 3.777,3.386 3.782,3.414 3.789,3.442 3.797,3.47 3.807,3.497 3.818,3.524 3.83,3.55 3.844,3.575 3.859,3.6 3.875,3.623 3.893,3.646 3.911,3.668 3.931,3.689 3.952,3.709 3.974,3.727 3.997,3.745 4.02,3.761 4.045,3.776 4.07,3.79 4.096,3.802 4.123,3.813 4.15,3.823 4.178,3.831 4.206,3.838 4.234,3.843 4.263,3.847 4.291,3.849 4.32,3.85
  Bottom Layer region: 4.349,0.049 4.377,0.047 4.406,0.043 4.434,0.038 4.462,0.031 4.49,0.023 4.517,0.013 4.544,0.002 4.57,-0.01 4.595,-0.024 4.62,-0.039 4.643,-0.055 4.666,-0.073 4.688,-0.091 4.709,-0.111 4.729,-0.132 4.747,-0.154 4.765,-0.177 4.781,-0.2 4.796,-0.225 4.81,-0.25 4.822,-0.276 4.833,-0.303 4.843,-0.33 4.851,-0.358 4.858,-0.386 4.863,-0.414 4.867,-0.443 4.869,-0.471 4.87,-0.5 4.87,-1.1 4.869,-1.129 4.867,-1.157 4.863,-1.186 4.858,-1.214 4.851,-1.242 4.843,-1.27 4.833,-1.297 4.822,-1.324 4.81,-1.35 4.796,-1.375 4.781,-1.4 4.765,-1.423 4.747,-1.446 4.729,-1.468 4.709,-1.489 4.688,-1.509 4.666,-1.527 4.643,-1.545 4.62,-1.561 4.595,-1.576 4.57,-1.59 4.544,-1.602 4.517,-1.613 4.49,-1.623 4.462,-1.631 4.434,-1.638 4.406,-1.643 4.377,-1.647 4.349,-1.649 4.32,-1.65 4.291,-1.649 4.263,-1.647 4.234,-1.643 4.206,-1.638 4.178,-1.631 4.15,-1.623 4.123,-1.613 4.096,-1.602 4.07,-1.59 4.045,-1.576 4.02,-1.561 3.997,-1.545 3.974,-1.527 3.952,-1.509 3.931,-1.489 3.911,-1.468 3.893,-1.446 3.875,-1.423 3.859,-1.4 3.844,-1.375 3.83,-1.35 3.818,-1.324 3.807,-1.297 3.797,-1.27 3.789,-1.242 3.782,-1.214 3.777,-1.186 3.773,-1.157 3.771,-1.129 3.77,-1.1 3.77,-0.5 3.771,-0.471 3.773,-0.443 3.777,-0.414 3.782,-0.386 3.789,-0.358 3.797,-0.33 3.807,-0.303 3.818,-0.276 3.83,-0.25 3.844,-0.225 3.859,-0.2 3.875,-0.177 3.893,-0.154 3.911,-0.132 3.931,-0.111 3.952,-0.091 3.974,-0.073 3.997,-0.055 4.02,-0.039 4.045,-0.024 4.07,-0.01 4.096,0.002 4.123,0.013 4.15,0.023 4.178,0.031 4.206,0.038 4.234,0.043 4.263,0.047 4.291,0.049 4.32,0.05
  Bottom Layer region: -4.291,0.049 -4.263,0.047 -4.234,0.043 -4.206,0.038 -4.178,0.031 -4.15,0.023 -4.123,0.013 -4.096,0.002 -4.07,-0.01 -4.045,-0.024 -4.02,-0.039 -3.997,-0.055 -3.974,-0.073 -3.952,-0.091 -3.931,-0.111 -3.911,-0.132 -3.893,-0.154 -3.875,-0.177 -3.859,-0.2 -3.844,-0.225 -3.83,-0.25 -3.818,-0.276 -3.807,-0.303 -3.797,-0.33 -3.789,-0.358 -3.782,-0.386 -3.777,-0.414 -3.773,-0.443 -3.771,-0.471 -3.77,-0.5 -3.77,-1.1 -3.771,-1.129 -3.773,-1.157 -3.777,-1.186 -3.782,-1.214 -3.789,-1.242 -3.797,-1.27 -3.807,-1.297 -3.818,-1.324 -3.83,-1.35 -3.844,-1.375 -3.859,-1.4 -3.875,-1.423 -3.893,-1.446 -3.911,-1.468 -3.931,-1.489 -3.952,-1.509 -3.974,-1.527 -3.997,-1.545 -4.02,-1.561 -4.045,-1.576 -4.07,-1.59 -4.096,-1.602 -4.123,-1.613 -4.15,-1.623 -4.178,-1.631 -4.206,-1.638 -4.234,-1.643 -4.263,-1.647 -4.291,-1.649 -4.32,-1.65 -4.349,-1.649 -4.377,-1.647 -4.406,-1.643 -4.434,-1.638 -4.462,-1.631 -4.49,-1.623 -4.517,-1.613 -4.544,-1.602 -4.57,-1.59 -4.595,-1.576 -4.62,-1.561 -4.643,-1.545 -4.666,-1.527 -4.688,-1.509 -4.709,-1.489 -4.729,-1.468 -4.747,-1.446 -4.765,-1.423 -4.781,-1.4 -4.796,-1.375 -4.81,-1.35 -4.822,-1.324 -4.833,-1.297 -4.843,-1.27 -4.851,-1.242 -4.858,-1.214 -4.863,-1.186 -4.867,-1.157 -4.869,-1.129 -4.87,-1.1 -4.87,-0.5 -4.869,-0.471 -4.867,-0.443 -4.863,-0.414 -4.858,-0.386 -4.851,-0.358 -4.843,-0.33 -4.833,-0.303 -4.822,-0.276 -4.81,-0.25 -4.796,-0.225 -4.781,-0.2 -4.765,-0.177 -4.747,-0.154 -4.729,-0.132 -4.709,-0.111 -4.688,-0.091 -4.666,-0.073 -4.643,-0.055 -4.62,-0.039 -4.595,-0.024 -4.57,-0.01 -4.544,0.002 -4.517,0.013 -4.49,0.023 -4.462,0.031 -4.434,0.038 -4.406,0.043 -4.377,0.047 -4.349,0.049 -4.32,0.05
  Bottom Layer region: -4.291,3.849 -4.263,3.847 -4.234,3.843 -4.206,3.838 -4.178,3.831 -4.15,3.823 -4.123,3.813 -4.096,3.802 -4.07,3.79 -4.045,3.776 -4.02,3.761 -3.997,3.745 -3.974,3.727 -3.952,3.709 -3.931,3.689 -3.911,3.668 -3.893,3.646 -3.875,3.623 -3.859,3.6 -3.844,3.575 -3.83,3.55 -3.818,3.524 -3.807,3.497 -3.797,3.47 -3.789,3.442 -3.782,3.414 -3.777,3.386 -3.773,3.357 -3.771,3.329 -3.77,3.3 -3.77,2.7 -3.771,2.671 -3.773,2.643 -3.777,2.614 -3.782,2.586 -3.789,2.558 -3.797,2.53 -3.807,2.503 -3.818,2.476 -3.83,2.45 -3.844,2.425 -3.859,2.4 -3.875,2.377 -3.893,2.354 -3.911,2.332 -3.931,2.311 -3.952,2.291 -3.974,2.273 -3.997,2.255 -4.02,2.239 -4.045,2.224 -4.07,2.21 -4.096,2.198 -4.123,2.187 -4.15,2.177 -4.178,2.169 -4.206,2.162 -4.234,2.157 -4.263,2.153 -4.291,2.151 -4.32,2.15 -4.349,2.151 -4.377,2.153 -4.406,2.157 -4.434,2.162 -4.462,2.169 -4.49,2.177 -4.517,2.187 -4.544,2.198 -4.57,2.21 -4.595,2.224 -4.62,2.239 -4.643,2.255 -4.666,2.273 -4.688,2.291 -4.709,2.311 -4.729,2.332 -4.747,2.354 -4.765,2.377 -4.781,2.4 -4.796,2.425 -4.81,2.45 -4.822,2.476 -4.833,2.503 -4.843,2.53 -4.851,2.558 -4.858,2.586 -4.863,2.614 -4.867,2.643 -4.869,2.671 -4.87,2.7 -4.87,3.3 -4.869,3.329 -4.867,3.357 -4.863,3.386 -4.858,3.414 -4.851,3.442 -4.843,3.47 -4.833,3.497 -4.822,3.524 -4.81,3.55 -4.796,3.575 -4.781,3.6 -4.765,3.623 -4.747,3.646 -4.729,3.668 -4.709,3.689 -4.688,3.709 -4.666,3.727 -4.643,3.745 -4.62,3.761 -4.595,3.776 -4.57,3.79 -4.544,3.802 -4.517,3.813 -4.49,3.823 -4.462,3.831 -4.434,3.838 -4.406,3.843 -4.377,3.847 -4.349,3.849 -4.32,3.85
  silkscreen extent -4.47,-3.4 4.47,-2.25
J110-ND [mm]
  round 1.72 hole 1.32: 1(0,0) 1(10.16,0)
  silkscreen extent 0,-2 10.16,2
LED_SML-M13DT_ROM [mil]
  rect 20x35 smd paste+0 mask+0: 1(-29.5,0) 2(29.5,0)
  Top Layer keep-out region: -17.5,-22.5 -17.5,22.5 17.5,22.5 17.5,-22.5
  silkscreen extent -130,-30 14,30
POT_PV36W_MUR [mil]
  rect 54x54 hole 34 paste-99999 mask+0: 1(0,0)
  round 54 hole 34 paste-99999 mask+0: 2(98.43,0) 3(196.85,0)
  silkscreen extent -96,-153 292,104, body extent -79,-98 299,99, height 377
PW14 [mil]
  rect 66x14 smd paste-33 mask-33: 1(-111,76.77) 2(-111,51.18) 3(-111,25.59) 4(-111,0) 5(-111,-25.59) 6(-111,-51.18) 7(-111,-76.77) 8(111,-76.77) 9(111,-51.18) 10(111,-25.59) 11(111,0) 12(111,25.59) 13(111,51.18) 14(111,76.77)
  silkscreen extent -89,-101 164,101, body extent -130,-101 130,101, height 47
R_8_ADI [mil]
  rect 78x22 smd paste+0 mask+0: 1(-97,75) 2(-97,25) 3(-97,-25) 4(-97,-75) 5(97,-75) 6(97,-25) 7(97,25) 8(97,75)
  silkscreen extent -84,-104 84,104, body extent -122,-99 122,99, height 69
RESISTOR_0805-M [mil]
  rect 36x55 smd paste+0 mask+0: 1(-37.5,0) 2(37.5,0)
  Top Layer keep-out region: -17.5,27.5 -17.5,-27.5 17.5,-27.5 17.5,27.5
  silkscreen extent -7,-32 7,32, body extent -44,-26 44,26, height 26
RJ_5_ADI [mil]
  rect 50x20 smd paste+0 mask+0: 1(-48,37.4) 2(-48,0) 3(-48,-37.4) 4(48,-37.4) 5(48,37.4)
  silkscreen extent -39,-64 39,64, body extent -59,-59 59,59, height 57
RU_16_ADI [mil]
  rect 58x14 smd paste+0 mask+0: 1(-111,89.57) 2(-111,63.98) 3(-111,38.39) 4(-111,12.8) 5(-111,-12.8) 6(-111,-38.39) 7(-111,-63.98) 8(-111,-89.57) 9(111,-89.57) 10(111,-63.98) 11(111,-38.39) 12(111,-12.8) 13(111,12.8) 14(111,38.39) 15(111,63.98) 16(111,89.57)
  silkscreen extent -72,-106 160,106, body extent -126,-101 126,101, height 47
SOP65P490X110-8N [mm]
  rrect25% 1.47x0.48 smd paste+0 mask+0.102: 1(-2.15,0.975) 2(-2.15,0.325) 3(-2.15,-0.325) 4(-2.15,-0.975) 5(2.15,-0.975) 6(2.15,-0.325) 7(2.15,0.325) 8(2.15,0.975)
  silkscreen extent -3.62,-1.54 1.5,1.54, body extent -2.45,-1.5 2.45,1.5, height 1.1
SOT-23_ONS [mil]
  rect 22x56 smd paste+0 mask+0: 1(-37.5,-38) 2(37.5,-38) 3(0,38)
  silkscreen extent -115,-57 65,32, body extent -60,-52 60,52, height 44
SWITCH_03211B [mil]
  round 67 hole 47 paste-99999 mask+0: 1(0,0) 6(0,-208.66)
  silkscreen extent -583,-345 -23,137
Testpoint1 [mil]
  round 60 hole 40: 1(0,0)
WCAP-ASLL_4X5.5(DXL) [mm]
  rect 2.6x1.6 smd: 1(1.8,0) 2(-1.8,0)
  silkscreen extent -2.25,-2.25 2.25,2.25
